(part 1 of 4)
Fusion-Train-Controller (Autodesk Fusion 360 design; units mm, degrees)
parameter "FrameLength" = 640 comment "Fixed existing outer length"
parameter "FrameWidth" = 190 comment "Fixed existing outer width"
parameter "FrameHeight" = 110 comment "Fixed existing height"
parameter "PivotHeight" = 65 comment "Above frame center"
parameter "LeverTravel" = 100 comment "Stable endpoint to endpoint"
parameter "PrintClearance" = 0.3 comment "Prototype diametral running clearance"
base_mesh_feature "Base Mesh Feature"
ground "Pin1"
work_plane "WorkPlane1" AlongDistance -36 ExtraOffset 0
sketch "Flat load-bearing plate" plane through (-36, 0, 0) normal (1, 0, 0) x axis (0, 0, -1)
  line L1 (-33, -55) -> (-33, -75)
  line L2 (2, -55) -> (-33, -55)
  line L3 (2, 55) -> (2, -55)
  line L4 (-33, 55) -> (2, 55)
  line L5 (-33, 75) -> (-33, 55)
  line L6 (-57, 75) -> (-33, 75)
  line L7 (-57, 32) -> (-57, 75)
  line L8 (-86, 26) -> (-57, 32)
  line L9 (-86, -26) -> (-86, 26)
  line L10 (-57, -32) -> (-86, -26)
  line L11 (-57, -75) -> (-57, -32)
  line L12 (-33, -75) -> (-57, -75)
extrude "Extrude1" new body sketch "Flat load-bearing plate" along normal blind 12
work_plane "WorkPlane2" AlongDistance -37 ExtraOffset 0
sketch "Replaceable bushing seat" plane through (-37, 0, 0) normal (1, 0, 0) x axis (0, 0, -1)
  circle C1 centre (-65, 0) radius 10.15
extrude "Extrude2" cut sketch "Replaceable bushing seat" along normal blind 14
work_plane "WorkPlane3" AlongDistance -37 ExtraOffset 0
sketch "Follower pivot bolt" plane through (-37, 0, 0) normal (1, 0, 0) x axis (0, 0, -1)
  circle C1 centre (-12, -35) radius 2.7
extrude "Extrude3" cut sketch "Follower pivot bolt" along normal blind 14
work_plane "WorkPlane4" AlongDistance -76 ExtraOffset 0
sketch "M5 rail mounting bore" plane through (0, -76, 0) normal (0, 1, 0) x axis (1, 0, 0)
  circle C1 centre (-30, -45) radius 2.7
extrude "Extrude4" cut sketch "M5 rail mounting bore" along normal blind 22
work_plane "WorkPlane5" AlongDistance -55 ExtraOffset 0
sketch "Rail screw tool and washer access" plane through (0, -55, 0) normal (0, 1, 0) x axis (1, 0, 0)
  circle C1 centre (-30, -45) radius 5.3
extrude "Extrude5" cut sketch "Rail screw tool and washer access" along normal blind 12
work_plane "WorkPlane6" AlongDistance 54 ExtraOffset 0
sketch "M5 rail mounting bore (1)" plane through (0, 54, 0) normal (0, 1, 0) x axis (1, 0, 0)
  circle C1 centre (-30, -45) radius 2.7
extrude "Extrude6" cut sketch "M5 rail mounting bore (1)" along normal blind 22
work_plane "WorkPlane7" AlongDistance 43 ExtraOffset 0
sketch "Rail screw tool and washer access (1)" plane through (0, 43, 0) normal (0, 1, 0) x axis (1, 0, 0)
  circle C1 centre (-30, -45) radius 5.3
extrude "Extrude7" cut sketch "Rail screw tool and washer access (1)" along normal blind 12
work_plane "WorkPlane8" AlongDistance -37 ExtraOffset 0
sketch "Spring crossblock attachment" plane through (-37, 0, 0) normal (1, 0, 0) x axis (0, 0, -1)
  circle C1 centre (-44, -59) radius 1.7
extrude "Extrude8" cut sketch "Spring crossblock attachment" along normal blind 14
work_plane "WorkPlane9" AlongDistance -37 ExtraOffset 0
sketch "Spring crossblock attachment (1)" plane through (-37, 0, 0) normal (1, 0, 0) x axis (0, 0, -1)
  circle C1 centre (-44, -51) radius 1.7
extrude "Extrude9" cut sketch "Spring crossblock attachment (1)" along normal blind 14
work_plane "WorkPlane1" AlongDistance 24 ExtraOffset 0
sketch "Flat load-bearing plate" plane through (24, 0, 0) normal (1, 0, 0) x axis (0, 0, -1)
  line L1 (-33, -55) -> (-33, -75)
  line L2 (2, -55) -> (-33, -55)
  line L3 (2, 55) -> (2, -55)
  line L4 (-33, 55) -> (2, 55)
  line L5 (-33, 75) -> (-33, 55)
  line L6 (-57, 75) -> (-33, 75)
  line L7 (-57, 32) -> (-57, 75)
  line L8 (-86, 26) -> (-57, 32)
  line L9 (-86, -26) -> (-86, 26)
  line L10 (-57, -32) -> (-86, -26)
  line L11 (-57, -75) -> (-57, -32)
  line L12 (-33, -75) -> (-57, -75)
extrude "Extrude1" new body sketch "Flat load-bearing plate" along normal blind 12
work_plane "WorkPlane2" AlongDistance 23 ExtraOffset 0
sketch "Replaceable bushing seat" plane through (23, 0, 0) normal (1, 0, 0) x axis (0, 0, -1)
  circle C1 centre (-65, 0) radius 10.15
extrude "Extrude2" cut sketch "Replaceable bushing seat" along normal blind 14
work_plane "WorkPlane3" AlongDistance 23 ExtraOffset 0
sketch "Follower pivot bolt" plane through (23, 0, 0) normal (1, 0, 0) x axis (0, 0, -1)
  circle C1 centre (-12, -35) radius 2.7
extrude "Extrude3" cut sketch "Follower pivot bolt" along normal blind 14
work_plane "WorkPlane4" AlongDistance -76 ExtraOffset 0
sketch "M5 rail mounting bore" plane through (0, -76, 0) normal (0, 1, 0) x axis (1, 0, 0)
  circle C1 centre (30, -45) radius 2.7
extrude "Extrude4" cut sketch "M5 rail mounting bore" along normal blind 22
work_plane "WorkPlane5" AlongDistance -55 ExtraOffset 0
sketch "Rail screw tool and washer access" plane through (0, -55, 0) normal (0, 1, 0) x axis (1, 0, 0)
  circle C1 centre (30, -45) radius 5.3
extrude "Extrude5" cut sketch "Rail screw tool and washer access" along normal blind 12
work_plane "WorkPlane6" AlongDistance 54 ExtraOffset 0
sketch "M5 rail mounting bore (1)" plane through (0, 54, 0) normal (0, 1, 0) x axis (1, 0, 0)
  circle C1 centre (30, -45) radius 2.7
extrude "Extrude6" cut sketch "M5 rail mounting bore (1)" along normal blind 22
work_plane "WorkPlane7" AlongDistance 43 ExtraOffset 0
sketch "Rail screw tool and washer access (1)" plane through (0, 43, 0) normal (0, 1, 0) x axis (1, 0, 0)
  circle C1 centre (30, -45) radius 5.3
extrude "Extrude7" cut sketch "Rail screw tool and washer access (1)" along normal blind 12
work_plane "WorkPlane8" AlongDistance 23 ExtraOffset 0
sketch "Spring crossblock attachment" plane through (23, 0, 0) normal (1, 0, 0) x axis (0, 0, -1)
  circle C1 centre (-44, -59) radius 1.7
extrude "Extrude8" cut sketch "Spring crossblock attachment" along normal blind 14
work_plane "WorkPlane9" AlongDistance 23 ExtraOffset 0
sketch "Spring crossblock attachment (1)" plane through (23, 0, 0) normal (1, 0, 0) x axis (0, 0, -1)
  circle C1 centre (-44, -51) radius 1.7
extrude "Extrude9" cut sketch "Spring crossblock attachment (1)" along normal blind 14
work_plane "WorkPlane1" AlongDistance -36 ExtraOffset 0
sketch "Replaceable journal body" plane through (-36, 0, 0) normal (1, 0, 0) x axis (0, 0, -1)
  circle C1 centre (-65, 0) radius 10.05
extrude "Extrude1" new body sketch "Replaceable journal body" along normal blind 12 bodies "P03 Left flanged journal bush"
work_plane "WorkPlane2" AlongDistance -37.2 ExtraOffset 0
sketch "Axial thrust flange" plane through (-37.2, 0, 0) normal (1, 0, 0) x axis (0, 0, -1)
  circle C1 centre (-65, 0) radius 12.75
extrude "Extrude2" add sketch "Axial thrust flange" along normal blind 1.2
work_plane "WorkPlane3" AlongDistance -38 ExtraOffset 0
sketch "Running journal bore" plane through (-38, 0, 0) normal (1, 0, 0) x axis (0, 0, -1)
  circle C1 centre (-65, 0) radius 6.15
extrude "Extrude3" cut sketch "Running journal bore" along normal blind 15
work_plane "WorkPlane1" AlongDistance 24 ExtraOffset 0
sketch "Replaceable journal body" plane through (24, 0, 0) normal (1, 0, 0) x axis (0, 0, -1)
  circle C1 centre (-65, 0) radius 10.05
extrude "Extrude1" new body sketch "Replaceable journal body" along normal blind 12 bodies "P04 Right flanged journal bush"
work_plane "WorkPlane2" AlongDistance 36 ExtraOffset 0
sketch "Axial thrust flange" plane through (36, 0, 0) normal (1, 0, 0) x axis (0, 0, -1)
  circle C1 centre (-65, 0) radius 12.75
extrude "Extrude2" add sketch "Axial thrust flange" along normal blind 1.2
work_plane "WorkPlane3" AlongDistance 23 ExtraOffset 0
sketch "Running journal bore" plane through (23, 0, 0) normal (1, 0, 0) x axis (0, 0, -1)
  circle C1 centre (-65, 0) radius 6.15
extrude "Extrude3" cut sketch "Running journal bore" along normal blind 15
work_plane "WorkPlane1" AlongDistance -37.35 ExtraOffset 0
sketch "Continuous 12 mm journals" plane through (-37.35, 0, 0) normal (1, 0, 0) x axis (0, 0, -1)
  circle C1 centre (-65, 0) radius 6
extrude "Extrude1" new body sketch "Continuous 12 mm journals" along normal blind 74.7 bodies "P05 Printed main shaft - horizontal print"
work_plane "WorkPlane2" AlongDistance -23.8 ExtraOffset 0
sketch "16 mm structural shaft" plane through (-23.8, 0, 0) normal (1, 0, 0) x axis (0, 0, -1)
  circle C1 centre (-65, 0) radius 8
extrude "Extrude2" add sketch "16 mm structural shaft" along normal blind 47.6
work_plane "WorkPlane3" AlongDistance -23.9 ExtraOffset 0
sketch "D-flat torque key" plane through (-23.9, 0, 0) normal (1, 0, 0) x axis (0, 0, -1)
  line L1 (-56, 9) -> (-56, 6.5)
  line L2 (-74, 9) -> (-56, 9)
  line L3 (-74, 6.5) -> (-74, 9)
  line L4 (-56, 6.5) -> (-74, 6.5)
extrude "Extrude3" cut sketch "D-flat torque key" along normal blind 47.8
work_plane "WorkPlane4" AlongDistance 37.35 ExtraOffset 0
sketch "Integral axial shoulder" plane through (37.35, 0, 0) normal (1, 0, 0) x axis (0, 0, -1)
  circle C1 centre (-65, 0) radius 10
extrude "Extrude4" add sketch "Integral axial shoulder" along normal blind 3
work_plane "WorkPlane5" AlongDistance 40.35 ExtraOffset 0
sketch "Sensor drive stub" plane through (40.35, 0, 0) normal (1, 0, 0) x axis (0, 0, -1)
  circle C1 centre (-65, 0) radius 4
extrude "Extrude5" add sketch "Sensor drive stub" along normal blind 10
work_plane "WorkPlane6" AlongDistance 40.25 ExtraOffset 0
sketch "Sensor drive flat" plane through (40.25, 0, 0) normal (1, 0, 0) x axis (0, 0, -1)
  line L1 (-60, 5) -> (-60, 3.2)
  line L2 (-70, 5) -> (-60, 5)
  line L3 (-70, 3.2) -> (-70, 5)
  line L4 (-60, 3.2) -> (-70, 3.2)
extrude "Extrude6" cut sketch "Sensor drive flat" along normal blind 10.25
work_plane "WorkPlane7" AlongDistance -37.45 ExtraOffset 0
sketch "M3 heat-set end retention" plane through (-37.45, 0, 0) normal (1, 0, 0) x axis (0, 0, -1)
  circle C1 centre (-65, 0) radius 2
extrude "Extrude7" cut sketch "M3 heat-set end retention" along normal blind 6.8
work_plane "WorkPlane1" AlongDistance -39.35 ExtraOffset 0
sketch "Axial cap" plane through (-39.35, 0, 0) normal (1, 0, 0) x axis (0, 0, -1)
  circle C1 centre (-65, 0) radius 10
extrude "Extrude1" new body sketch "Axial cap" along normal blind 2 bodies "P06 Shaft retaining cap"
work_plane "WorkPlane2" AlongDistance -39.5 ExtraOffset 0
sketch "M3 cap screw" plane through (-39.5, 0, 0) normal (1, 0, 0) x axis (0, 0, -1)
  circle C1 centre (-65, 0) radius 1.7
extrude "Extrude2" cut sketch "M3 cap screw" along normal blind 2.4
work_plane "WorkPlane1" AlongDistance -7 ExtraOffset 0
sketch "Main lever hub" plane through (-7, 0, 0) normal (1, 0, 0) x axis (0, 0, -1)
  circle C1 centre (-65, 0) radius 22
extrude "Extrude1" new body sketch "Main lever hub" along normal blind 14 bodies "P07 Integral lever rotor and cam carrier"
work_plane "WorkPlane2" AlongDistance -7 ExtraOffset 0
sketch "Continuous reinforced lever stem" plane through (-7, 0, 0) normal (1, 0, 0) x axis (0, 0, -1)
  line L1 (-60, 14) -> (-60, -14)
  line L2 (-95, 11) -> (-60, 14)
  line L3 (-150, 7) -> (-95, 11)
  line L4 (-195, 7) -> (-150, 7)
  line L5 (-195, -7) -> (-195, 7)
  line L6 (-150, -7) -> (-195, -7)
  line L7 (-95, -11) -> (-150, -7)
  line L8 (-60, -14) -> (-95, -11)
extrude "Extrude2" add sketch "Continuous reinforced lever stem" along normal blind 14
work_plane "WorkPlane3" AlongDistance -7 ExtraOffset 0
sketch "Integrated cam carrier fan" plane through (-7, 0, 0) normal (1, 0, 0) x axis (0, 0, -1)
  line L1 (-44.5, 35.507) -> (-65, 0)
  line L2 (-42.6698, 34.3855) -> (-44.5, 35.507)
  line L3 (-40.9008, 33.1697) -> (-42.6698, 34.3855)
  line L4 (-39.1979, 31.863) -> (-40.9008, 33.1697)
  line L5 (-37.5656, 30.4689) -> (-39.1979, 31.863)
  line L6 (-36.0086, 28.9914) -> (-37.5656, 30.4689)
  line L7 (-34.5311, 27.4344) -> (-36.0086, 28.9914)
  line L8 (-33.137, 25.8021) -> (-34.5311, 27.4344)
  line L9 (-31.8303, 24.0992) -> (-33.137, 25.8021)
  line L10 (-30.6145, 22.3302) -> (-31.8303, 24.0992)
  line L11 (-29.493, 20.5) -> (-30.6145, 22.3302)
  line L12 (-28.4687, 18.6136) -> (-29.493, 20.5)
  line L13 (-27.5446, 16.6762) -> (-28.4687, 18.6136)
  line L14 (-26.7232, 14.6931) -> (-27.5446, 16.6762)
  line L15 (-26.0067, 12.6697) -> (-26.7232, 14.6931)
  line L16 (-25.397, 10.6116) -> (-26.0067, 12.6697)
  line L17 (-24.8959, 8.5244) -> (-25.397, 10.6116)
  line L18 (-24.5048, 6.4138) -> (-24.8959, 8.5244)
  line L19 (-24.2246, 4.2857) -> (-24.5048, 6.4138)
  line L20 (-24.0562, 2.1458) -> (-24.2246, 4.2857)
  line L21 (-24, 0) -> (-24.0562, 2.1458)
  line L22 (-24.0562, -2.1458) -> (-24, 0)
  line L23 (-24.2246, -4.2857) -> (-24.0562, -2.1458)
  line L24 (-24.5048, -6.4138) -> (-24.2246, -4.2857)
  line L25 (-24.8959, -8.5244) -> (-24.5048, -6.4138)
  line L26 (-25.397, -10.6116) -> (-24.8959, -8.5244)
  line L27 (-26.0067, -12.6697) -> (-25.397, -10.6116)
  line L28 (-26.7232, -14.6931) -> (-26.0067, -12.6697)
  line L29 (-27.5446, -16.6762) -> (-26.7232, -14.6931)
  line L30 (-28.4687, -18.6136) -> (-27.5446, -16.6762)
  line L31 (-29.493, -20.5) -> (-28.4687, -18.6136)
  line L32 (-30.6145, -22.3302) -> (-29.493, -20.5)
  line L33 (-31.8303, -24.0992) -> (-30.6145, -22.3302)
  line L34 (-33.137, -25.8021) -> (-31.8303, -24.0992)
  line L35 (-34.5311, -27.4344) -> (-33.137, -25.8021)
  line L36 (-36.0086, -28.9914) -> (-34.5311, -27.4344)
  line L37 (-37.5656, -30.4689) -> (-36.0086, -28.9914)
  line L38 (-39.1979, -31.863) -> (-37.5656, -30.4689)
  line L39 (-40.9008, -33.1697) -> (-39.1979, -31.863)
  line L40 (-42.6698, -34.3855) -> (-40.9008, -33.1697)
  line L41 (-44.5, -35.507) -> (-42.6698, -34.3855)
  line L42 (-65, 0) -> (-44.5, -35.507)
extrude "Extrude3" add sketch "Integrated cam carrier fan" along normal blind 14
work_plane "WorkPlane4" AlongDistance -23.6 ExtraOffset 0
sketch "Integral axial locating hub" plane through (-23.6, 0, 0) normal (1, 0, 0) x axis (0, 0, -1)
  circle C1 centre (-65, 0) radius 10
work_plane "WorkPlane5" AlongDistance -24 ExtraOffset 0
sketch "D shaft socket" plane through (-24, 0, 0) normal (1, 0, 0) x axis (0, 0, -1)
  line L1 (-69.6247, 6.65) -> (-60.3753, 6.65)
  arc A1 centre (-65, 0) radius 8.1 clockwise from (-60.3753, 6.65) to (-69.6247, 6.65)
extrude "Extrude5" cut sketch "D shaft socket" along normal blind 48
work_plane "WorkPlane6" AlongDistance 0.3 ExtraOffset 0
sketch "Cam M3 insert pocket" plane through (0.3, 0, 0) normal (1, 0, 0) x axis (0, 0, -1)
  circle C1 centre (-39.5442, 25.4558) radius 2
extrude "Extrude6" cut sketch "Cam M3 insert pocket" along normal blind 6.8
work_plane "WorkPlane7" AlongDistance 0.3 ExtraOffset 0
sketch "Cam M3 insert pocket (1)" plane through (0.3, 0, 0) normal (1, 0, 0) x axis (0, 0, -1)
  circle C1 centre (-29, 0) radius 2
extrude "Extrude7" cut sketch "Cam M3 insert pocket (1)" along normal blind 6.8
work_plane "WorkPlane8" AlongDistance 0.3 ExtraOffset 0
sketch "Cam M3 insert pocket (2)" plane through (0.3, 0, 0) normal (1, 0, 0) x axis (0, 0, -1)
  circle C1 centre (-39.5442, -25.4558) radius 2
extrude "Extrude8" cut sketch "Cam M3 insert pocket (2)" along normal blind 6.8
work_plane "WorkPlane9" AlongDistance -8 ExtraOffset 0
sketch "Grip through bolt" plane through (-8, 0, 0) normal (1, 0, 0) x axis (0, 0, -1)
  circle C1 centre (-180, 0) radius 1.7
extrude "Extrude9" cut sketch "Grip through bolt" along normal blind 16
work_plane "WorkPlane10" AlongDistance -8 ExtraOffset 0
sketch "Grip through bolt (1)" plane through (-8, 0, 0) normal (1, 0, 0) x axis (0, 0, -1)
  circle C1 centre (-190, 0) radius 1.7
extrude "Extrude10" cut sketch "Grip through bolt (1)" along normal blind 16
work_plane "WorkPlane1" AlongDistance 7 ExtraOffset 0
sketch "Roller compensated replaceable cam" plane through (7, 0, 0) normal (1, 0, 0) x axis (0, 0, -1)
  line L1 (-39.4967, 42.2602) -> (-39.6212, 42.3096)
  line L2 (-39.3834, 42.211) -> (-39.4967, 42.2602)
  line L3 (-39.2796, 42.1617) -> (-39.3834, 42.211)
  line L4 (-39.1836, 42.1119) -> (-39.2796, 42.1617)
  line L5 (-39.0932, 42.0608) -> (-39.1836, 42.1119)
  line L6 (-39.0065, 42.0075) -> (-39.0932, 42.0608)
  line L7 (-38.9215, 41.9508) -> (-39.0065, 42.0075)
  line L8 (-38.8363, 41.8895) -> (-38.9215, 41.9508)
  line L9 (-38.7492, 41.8219) -> (-38.8363, 41.8895)
  line L10 (-38.6586, 41.7465) -> (-38.7492, 41.8219)
  line L11 (-38.5633, 41.6619) -> (-38.6586, 41.7465)
  line L12 (-38.4623, 41.5665) -> (-38.5633, 41.6619)
  line L13 (-38.3549, 41.459) -> (-38.4623, 41.5665)
  line L14 (-38.2404, 41.3384) -> (-38.3549, 41.459)
  line L15 (-38.1184, 41.204) -> (-38.2404, 41.3384)
  line L16 (-37.9886, 41.055) -> (-38.1184, 41.204)
  line L17 (-37.8508, 40.8913) -> (-37.9886, 41.055)
  line L18 (-37.7045, 40.7127) -> (-37.8508, 40.8913)
  line L19 (-37.5496, 40.5196) -> (-37.7045, 40.7127)
  line L20 (-37.3856, 40.3123) -> (-37.5496, 40.5196)
  line L21 (-37.2122, 40.0915) -> (-37.3856, 40.3123)
  line L22 (-37.0289, 39.858) -> (-37.2122, 40.0915)
  line L23 (-36.8353, 39.6128) -> (-37.0289, 39.858)
  line L24 (-36.6306, 39.3571) -> (-36.8353, 39.6128)
  line L25 (-36.4145, 39.0923) -> (-36.6306, 39.3571)
  line L26 (-36.1865, 38.82) -> (-36.4145, 39.0923)
  line L27 (-35.9461, 38.5417) -> (-36.1865, 38.82)
  line L28 (-35.6932, 38.2594) -> (-35.9461, 38.5417)
  line L29 (-35.4277, 37.9751) -> (-35.6932, 38.2594)
  line L30 (-35.15, 37.6908) -> (-35.4277, 37.9751)
  line L31 (-34.8607, 37.4087) -> (-35.15, 37.6908)
  line L32 (-34.5606, 37.1307) -> (-34.8607, 37.4087)
  line L33 (-34.2512, 36.859) -> (-34.5606, 37.1307)
  line L34 (-33.934, 36.5953) -> (-34.2512, 36.859)
  line L35 (-33.6109, 36.341) -> (-33.934, 36.5953)
  line L36 (-33.2841, 36.0975) -> (-33.6109, 36.341)
  line L37 (-32.9558, 35.8655) -> (-33.2841, 36.0975)
  line L38 (-32.6282, 35.6454) -> (-32.9558, 35.8655)
  line L39 (-32.3036, 35.4375) -> (-32.6282, 35.6454)
  line L40 (-31.984, 35.2415) -> (-32.3036, 35.4375)
  line L41 (-31.6712, 35.057) -> (-31.984, 35.2415)
  line L42 (-31.3671, 34.8833) -> (-31.6712, 35.057)
  line L43 (-31.073, 34.7197) -> (-31.3671, 34.8833)
  line L44 (-30.7902, 34.5655) -> (-31.073, 34.7197)
  line L45 (-30.52, 34.4197) -> (-30.7902, 34.5655)
  line L46 (-30.263, 34.2816) -> (-30.52, 34.4197)
  line L47 (-30.0201, 34.1506) -> (-30.263, 34.2816)
  line L48 (-29.7919, 34.0259) -> (-30.0201, 34.1506)
  line L49 (-29.5787, 33.9071) -> (-29.7919, 34.0259)
  line L50 (-29.3807, 33.7939) -> (-29.5787, 33.9071)
  line L51 (-29.1982, 33.6858) -> (-29.3807, 33.7939)
  line L52 (-29.0309, 33.5827) -> (-29.1982, 33.6858)
  line L53 (-28.8786, 33.4843) -> (-29.0309, 33.5827)
  line L54 (-28.7406, 33.3906) -> (-28.8786, 33.4843)
  line L55 (-28.6164, 33.3013) -> (-28.7406, 33.3906)
  line L56 (-28.5047, 33.2161) -> (-28.6164, 33.3013)
  line L57 (-28.4046, 33.1346) -> (-28.5047, 33.2161)
  line L58 (-28.3144, 33.0563) -> (-28.4046, 33.1346)
  line L59 (-28.2327, 32.9802) -> (-28.3144, 33.0563)
  line L60 (-28.1577, 32.9052) -> (-28.2327, 32.9802)
  line L61 (-28.0879, 32.8301) -> (-28.1577, 32.9052)
  line L62 (-28.0214, 32.7532) -> (-28.0879, 32.8301)
  line L63 (-27.9569, 32.6728) -> (-28.0214, 32.7532)
  line L64 (-27.893, 32.5869) -> (-27.9569, 32.6728)
  line L65 (-27.8285, 32.4936) -> (-27.893, 32.5869)
  line L66 (-27.7627, 32.3911) -> (-27.8285, 32.4936)
  line L67 (-27.6947, 32.2776) -> (-27.7627, 32.3911)
  line L68 (-27.6241, 32.1514) -> (-27.6947, 32.2776)
  line L69 (-27.5507, 32.0113) -> (-27.6241, 32.1514)
  line L70 (-27.4742, 31.8562) -> (-27.5507, 32.0113)
  line L71 (-27.3945, 31.6853) -> (-27.4742, 31.8562)
  line L72 (-27.3113, 31.4981) -> (-27.3945, 31.6853)
  line L73 (-27.2245, 31.2943) -> (-27.3113, 31.4981)
  line L74 (-27.1338, 31.074) -> (-27.2245, 31.2943)
  line L75 (-27.0388, 30.8373) -> (-27.1338, 31.074)
  line L76 (-26.939, 30.5847) -> (-27.0388, 30.8373)
  line L77 (-26.8337, 30.3166) -> (-26.939, 30.5847)
  line L78 (-26.7223, 30.034) -> (-26.8337, 30.3166)
  line L79 (-26.6038, 29.7375) -> (-26.7223, 30.034)
  line L80 (-26.4775, 29.4284) -> (-26.6038, 29.7375)
  line L81 (-26.3424, 29.1079) -> (-26.4775, 29.4284)
  line L82 (-26.1977, 28.7772) -> (-26.3424, 29.1079)
  line L83 (-26.0425, 28.4382) -> (-26.1977, 28.7772)
  line L84 (-25.8761, 28.0925) -> (-26.0425, 28.4382)
  line L85 (-25.6981, 27.7422) -> (-25.8761, 28.0925)
  line L86 (-25.5084, 27.3893) -> (-25.6981, 27.7422)
  line L87 (-25.3069, 27.0362) -> (-25.5084, 27.3893)
  line L88 (-25.0943, 26.6851) -> (-25.3069, 27.0362)
  line L89 (-24.8713, 26.3382) -> (-25.0943, 26.6851)
  line L90 (-24.6392, 25.9976) -> (-24.8713, 26.3382)
  line L91 (-24.3995, 25.6653) -> (-24.6392, 25.9976)
  line L92 (-24.1539, 25.3428) -> (-24.3995, 25.6653)
  line L93 (-23.9045, 25.0314) -> (-24.1539, 25.3428)
  line L94 (-23.6532, 24.7321) -> (-23.9045, 25.0314)
  line L95 (-23.4022, 24.4455) -> (-23.6532, 24.7321)
  line L96 (-23.1534, 24.1718) -> (-23.4022, 24.4455)
  line L97 (-22.9088, 23.9111) -> (-23.1534, 24.1718)
  line L98 (-22.6701, 23.6631) -> (-22.9088, 23.9111)
  line L99 (-22.4387, 23.4276) -> (-22.6701, 23.6631)
  line L100 (-22.2162, 23.204) -> (-22.4387, 23.4276)
  line L101 (-22.0036, 22.9918) -> (-22.2162, 23.204)
  line L102 (-21.8021, 22.7907) -> (-22.0036, 22.9918)
  line L103 (-21.6123, 22.6001) -> (-21.8021, 22.7907)
  line L104 (-21.435, 22.4197) -> (-21.6123, 22.6001)
  line L105 (-21.2706, 22.2491) -> (-21.435, 22.4197)
  line L106 (-21.1193, 22.088) -> (-21.2706, 22.2491)
  line L107 (-20.9813, 21.9362) -> (-21.1193, 22.088)
  line L108 (-20.8565, 21.7934) -> (-20.9813, 21.9362)
  line L109 (-20.7443, 21.6594) -> (-20.8565, 21.7934)
  line L110 (-20.6444, 21.5337) -> (-20.7443, 21.6594)
  line L111 (-20.556, 21.4159) -> (-20.6444, 21.5337)
  line L112 (-20.478, 21.3055) -> (-20.556, 21.4159)
  line L113 (-20.4094, 21.2014) -> (-20.478, 21.3055)
  line L114 (-20.349, 21.1027) -> (-20.4094, 21.2014)
  line L115 (-20.2954, 21.0079) -> (-20.349, 21.1027)
  line L116 (-20.2475, 20.9154) -> (-20.2954, 21.0079)
  line L117 (-20.2039, 20.8234) -> (-20.2475, 20.9154)
  line L118 (-20.1637, 20.7297) -> (-20.2039, 20.8234)
  line L119 (-20.126, 20.6321) -> (-20.1637, 20.7297)
  line L120 (-20.0901, 20.5286) -> (-20.126, 20.6321)
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extrude "Extrude1" new body sketch "Roller compensated replaceable cam" along normal blind 8 bodies "P08 Cam 7 gates - stable endpoints"
work_plane "WorkPlane2" AlongDistance 6.9 ExtraOffset 0
sketch "Cam screw clearance" plane through (6.9, 0, 0) normal (1, 0, 0) x axis (0, 0, -1)
  circle C1 centre (-39.5442, 25.4558) radius 1.7
extrude "Extrude2" cut sketch "Cam screw clearance" along normal blind 8.2
work_plane "WorkPlane3" AlongDistance 12 ExtraOffset 0
sketch "Cam head recess" plane through (12, 0, 0) normal (1, 0, 0) x axis (0, 0, -1)
  circle C1 centre (-39.5442, 25.4558) radius 3.1
extrude "Extrude3" cut sketch "Cam head recess" along normal blind 3.1
work_plane "WorkPlane4" AlongDistance 6.9 ExtraOffset 0
sketch "Cam screw clearance (1)" plane through (6.9, 0, 0) normal (1, 0, 0) x axis (0, 0, -1)
  circle C1 centre (-29, 0) radius 1.7
extrude "Extrude4" cut sketch "Cam screw clearance (1)" along normal blind 8.2
work_plane "WorkPlane5" AlongDistance 12 ExtraOffset 0
sketch "Cam head recess (1)" plane through (12, 0, 0) normal (1, 0, 0) x axis (0, 0, -1)
  circle C1 centre (-29, 0) radius 3.1
extrude "Extrude5" cut sketch "Cam head recess (1)" along normal blind 3.1
work_plane "WorkPlane6" AlongDistance 6.9 ExtraOffset 0
sketch "Cam screw clearance (2)" plane through (6.9, 0, 0) normal (1, 0, 0) x axis (0, 0, -1)
  circle C1 centre (-39.5442, -25.4558) radius 1.7
extrude "Extrude6" cut sketch "Cam screw clearance (2)" along normal blind 8.2
work_plane "WorkPlane7" AlongDistance 12 ExtraOffset 0
sketch "Cam head recess (2)" plane through (12, 0, 0) normal (1, 0, 0) x axis (0, 0, -1)
  circle C1 centre (-39.5442, -25.4558) radius 3.1
extrude "Extrude7" cut sketch "Cam head recess (2)" along normal blind 3.1
work_plane "WorkPlane1" AlongDistance 7 ExtraOffset 0
sketch "Roller compensated replaceable cam" plane through (7, 0, 0) normal (1, 0, 0) x axis (0, 0, -1)
  line L1 (-40.6423, 42.8316) -> (-40.8055, 42.9534)
  line L2 (-40.4783, 42.705) -> (-40.6423, 42.8316)
  line L3 (-40.3132, 42.5736) -> (-40.4783, 42.705)
  line L4 (-40.1469, 42.4372) -> (-40.3132, 42.5736)
  line L5 (-39.9791, 42.2958) -> (-40.1469, 42.4372)
  line L6 (-39.8097, 42.1493) -> (-39.9791, 42.2958)
  line L7 (-39.6386, 41.9977) -> (-39.8097, 42.1493)
  line L8 (-39.4656, 41.8411) -> (-39.6386, 41.9977)
  line L9 (-39.2906, 41.6794) -> (-39.4656, 41.8411)
  line L10 (-39.1134, 41.5128) -> (-39.2906, 41.6794)
  line L11 (-38.9338, 41.3413) -> (-39.1134, 41.5128)
  line L12 (-38.7519, 41.165) -> (-38.9338, 41.3413)
  line L13 (-38.5674, 40.9842) -> (-38.7519, 41.165)
  line L14 (-38.3803, 40.7991) -> (-38.5674, 40.9842)
  line L15 (-38.1904, 40.6097) -> (-38.3803, 40.7991)
  line L16 (-37.9976, 40.4164) -> (-38.1904, 40.6097)
  line L17 (-37.8019, 40.2195) -> (-37.9976, 40.4164)
  line L18 (-37.6031, 40.0191) -> (-37.8019, 40.2195)
  line L19 (-37.4011, 39.8157) -> (-37.6031, 40.0191)
  line L20 (-37.1958, 39.6094) -> (-37.4011, 39.8157)
  line L21 (-36.9872, 39.4008) -> (-37.1958, 39.6094)
  line L22 (-36.7753, 39.19) -> (-36.9872, 39.4008)
  line L23 (-36.5599, 38.9775) -> (-36.7753, 39.19)
  line L24 (-36.3411, 38.7636) -> (-36.5599, 38.9775)
  line L25 (-36.1189, 38.5488) -> (-36.3411, 38.7636)
  line L26 (-35.8933, 38.3333) -> (-36.1189, 38.5488)
  line L27 (-35.6644, 38.1177) -> (-35.8933, 38.3333)
  line L28 (-35.4322, 37.9021) -> (-35.6644, 38.1177)
  line L29 (-35.197, 37.6871) -> (-35.4322, 37.9021)
  line L30 (-34.9588, 37.473) -> (-35.197, 37.6871)
  line L31 (-34.7178, 37.2602) -> (-34.9588, 37.473)
  line L32 (-34.4743, 37.0489) -> (-34.7178, 37.2602)
  line L33 (-34.2286, 36.8395) -> (-34.4743, 37.0489)
  line L34 (-33.9808, 36.6322) -> (-34.2286, 36.8395)
  line L35 (-33.7314, 36.4274) -> (-33.9808, 36.6322)
  line L36 (-33.4806, 36.2252) -> (-33.7314, 36.4274)
  line L37 (-33.2289, 36.0258) -> (-33.4806, 36.2252)
  line L38 (-32.9765, 35.8294) -> (-33.2289, 36.0258)
  line L39 (-32.7239, 35.6361) -> (-32.9765, 35.8294)
  line L40 (-32.4714, 35.446) -> (-32.7239, 35.6361)
  line L41 (-32.2195, 35.259) -> (-32.4714, 35.446)
  line L42 (-31.9685, 35.0753) -> (-32.2195, 35.259)
  line L43 (-31.7188, 34.8948) -> (-31.9685, 35.0753)
  line L44 (-31.4708, 34.7175) -> (-31.7188, 34.8948)
  line L45 (-31.2249, 34.5432) -> (-31.4708, 34.7175)
  line L46 (-30.9813, 34.3719) -> (-31.2249, 34.5432)
  line L47 (-30.7405, 34.2034) -> (-30.9813, 34.3719)
  line L48 (-30.5027, 34.0377) -> (-30.7405, 34.2034)
  line L49 (-30.2682, 33.8746) -> (-30.5027, 34.0377)
  line L50 (-30.0373, 33.7139) -> (-30.2682, 33.8746)
  line L51 (-29.8103, 33.5555) -> (-30.0373, 33.7139)
  line L52 (-29.5875, 33.3992) -> (-29.8103, 33.5555)
  line L53 (-29.3689, 33.2448) -> (-29.5875, 33.3992)
  line L54 (-29.1548, 33.0923) -> (-29.3689, 33.2448)
  line L55 (-28.9455, 32.9414) -> (-29.1548, 33.0923)
  line L56 (-28.7409, 32.7921) -> (-28.9455, 32.9414)
  line L57 (-28.5413, 32.644) -> (-28.7409, 32.7921)
  line L58 (-28.3468, 32.4972) -> (-28.5413, 32.644)
  line L59 (-28.1574, 32.3515) -> (-28.3468, 32.4972)
  line L60 (-27.9732, 32.2068) -> (-28.1574, 32.3515)
  line L61 (-27.7942, 32.0628) -> (-27.9732, 32.2068)
  line L62 (-27.6204, 31.9196) -> (-27.7942, 32.0628)
  line L63 (-27.4518, 31.7769) -> (-27.6204, 31.9196)
  line L64 (-27.2884, 31.6347) -> (-27.4518, 31.7769)
  line L65 (-27.1301, 31.4927) -> (-27.2884, 31.6347)
  line L66 (-26.9767, 31.351) -> (-27.1301, 31.4927)
  line L67 (-26.8282, 31.2092) -> (-26.9767, 31.351)
  line L68 (-26.6843, 31.0673) -> (-26.8282, 31.2092)
  line L69 (-26.545, 30.925) -> (-26.6843, 31.0673)
  line L70 (-26.4101, 30.7822) -> (-26.545, 30.925)
  line L71 (-26.2793, 30.6387) -> (-26.4101, 30.7822)
  line L72 (-26.1524, 30.4942) -> (-26.2793, 30.6387)
  line L73 (-26.0293, 30.3485) -> (-26.1524, 30.4942)
  line L74 (-25.9096, 30.2013) -> (-26.0293, 30.3485)
  line L75 (-25.7932, 30.0524) -> (-25.9096, 30.2013)
  line L76 (-25.6797, 29.9015) -> (-25.7932, 30.0524)
  line L77 (-25.5691, 29.7482) -> (-25.6797, 29.9015)
  line L78 (-25.461, 29.5923) -> (-25.5691, 29.7482)
  line L79 (-25.3553, 29.4334) -> (-25.461, 29.5923)
  line L80 (-25.2517, 29.2713) -> (-25.3553, 29.4334)
  line L81 (-25.15, 29.1057) -> (-25.2517, 29.2713)
  line L82 (-25.0502, 28.9363) -> (-25.15, 29.1057)
  line L83 (-24.9519, 28.7628) -> (-25.0502, 28.9363)
  line L84 (-24.855, 28.5849) -> (-24.9519, 28.7628)
  line L85 (-24.7595, 28.4024) -> (-24.855, 28.5849)
  line L86 (-24.665, 28.2152) -> (-24.7595, 28.4024)
  line L87 (-24.5716, 28.023) -> (-24.665, 28.2152)
  line L88 (-24.4791, 27.8257) -> (-24.5716, 28.023)
  line L89 (-24.3873, 27.6231) -> (-24.4791, 27.8257)
  line L90 (-24.2961, 27.4152) -> (-24.3873, 27.6231)
  line L91 (-24.2054, 27.2019) -> (-24.2961, 27.4152)
  line L92 (-24.115, 26.9832) -> (-24.2054, 27.2019)
  line L93 (-24.0247, 26.7591) -> (-24.115, 26.9832)
  line L94 (-23.9346, 26.5296) -> (-24.0247, 26.7591)
  line L95 (-23.8442, 26.2947) -> (-23.9346, 26.5296)
  line L96 (-23.7536, 26.0546) -> (-23.8442, 26.2947)
  line L97 (-23.6625, 25.8094) -> (-23.7536, 26.0546)
  line L98 (-23.5707, 25.5592) -> (-23.6625, 25.8094)
  line L99 (-23.478, 25.3041) -> (-23.5707, 25.5592)
  line L100 (-23.3842, 25.0444) -> (-23.478, 25.3041)
  line L101 (-23.2891, 24.7802) -> (-23.3842, 25.0444)
  line L102 (-23.1926, 24.5118) -> (-23.2891, 24.7802)
  line L103 (-23.0943, 24.2394) -> (-23.1926, 24.5118)
  line L104 (-22.9942, 23.9633) -> (-23.0943, 24.2394)
  line L105 (-22.8919, 23.6838) -> (-22.9942, 23.9633)
  line L106 (-22.7873, 23.4012) -> (-22.8919, 23.6838)
  line L107 (-22.6803, 23.1157) -> (-22.7873, 23.4012)
  line L108 (-22.5706, 22.8278) -> (-22.6803, 23.1157)
  line L109 (-22.4581, 22.5379) -> (-22.5706, 22.8278)
  line L110 (-22.3428, 22.2461) -> (-22.4581, 22.5379)
  line L111 (-22.2245, 21.953) -> (-22.3428, 22.2461)
  line L112 (-22.1031, 21.659) -> (-22.2245, 21.953)
  line L113 (-21.9788, 21.3644) -> (-22.1031, 21.659)
  line L114 (-21.8513, 21.0696) -> (-21.9788, 21.3644)
  line L115 (-21.7209, 20.7751) -> (-21.8513, 21.0696)
  line L116 (-21.5876, 20.4811) -> (-21.7209, 20.7751)
  line L117 (-21.4516, 20.1882) -> (-21.5876, 20.4811)
  line L118 (-21.3129, 19.8966) -> (-21.4516, 20.1882)
  line L119 (-21.1718, 19.6067) -> (-21.3129, 19.8966)
  line L120 (-21.0286, 19.3189) -> (-21.1718, 19.6067)
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extrude "Extrude1" new body sketch "Roller compensated replaceable cam" along normal blind 8 bodies "P08 Cam 5 gates - stable endpoints"
work_plane "WorkPlane2" AlongDistance 6.9 ExtraOffset 0
sketch "Cam screw clearance" plane through (6.9, 0, 0) normal (1, 0, 0) x axis (0, 0, -1)
  circle C1 centre (-39.5442, 25.4558) radius 1.7
extrude "Extrude2" cut sketch "Cam screw clearance" along normal blind 8.2
work_plane "WorkPlane3" AlongDistance 12 ExtraOffset 0
sketch "Cam head recess" plane through (12, 0, 0) normal (1, 0, 0) x axis (0, 0, -1)
  circle C1 centre (-39.5442, 25.4558) radius 3.1
extrude "Extrude3" cut sketch "Cam head recess" along normal blind 3.1
work_plane "WorkPlane4" AlongDistance 6.9 ExtraOffset 0
sketch "Cam screw clearance (1)" plane through (6.9, 0, 0) normal (1, 0, 0) x axis (0, 0, -1)
  circle C1 centre (-29, 0) radius 1.7
extrude "Extrude4" cut sketch "Cam screw clearance (1)" along normal blind 8.2
work_plane "WorkPlane5" AlongDistance 12 ExtraOffset 0
sketch "Cam head recess (1)" plane through (12, 0, 0) normal (1, 0, 0) x axis (0, 0, -1)
  circle C1 centre (-29, 0) radius 3.1
extrude "Extrude5" cut sketch "Cam head recess (1)" along normal blind 3.1
work_plane "WorkPlane6" AlongDistance 6.9 ExtraOffset 0
sketch "Cam screw clearance (2)" plane through (6.9, 0, 0) normal (1, 0, 0) x axis (0, 0, -1)
  circle C1 centre (-39.5442, -25.4558) radius 1.7
extrude "Extrude6" cut sketch "Cam screw clearance (2)" along normal blind 8.2
work_plane "WorkPlane7" AlongDistance 12 ExtraOffset 0
sketch "Cam head recess (2)" plane through (12, 0, 0) normal (1, 0, 0) x axis (0, 0, -1)
  circle C1 centre (-39.5442, -25.4558) radius 3.1
extrude "Extrude7" cut sketch "Cam head recess (2)" along normal blind 3.1
work_plane "WorkPlane1" AlongDistance 7 ExtraOffset 0
sketch "Roller compensated replaceable cam" plane through (7, 0, 0) normal (1, 0, 0) x axis (0, 0, -1)
  line L1 (-40.92, 42.0772) -> (-41.1325, 42.2273)
  line L2 (-40.7077, 41.9259) -> (-40.92, 42.0772)
  line L3 (-40.4956, 41.7734) -> (-40.7077, 41.9259)
  line L4 (-40.2838, 41.6199) -> (-40.4956, 41.7734)
  line L5 (-40.0721, 41.4654) -> (-40.2838, 41.6199)
  line L6 (-39.8606, 41.3098) -> (-40.0721, 41.4654)
  line L7 (-39.6492, 41.1532) -> (-39.8606, 41.3098)
  line L8 (-39.4381, 40.9957) -> (-39.6492, 41.1532)
  line L9 (-39.2271, 40.8372) -> (-39.4381, 40.9957)
  line L10 (-39.0163, 40.6779) -> (-39.2271, 40.8372)
  line L11 (-38.8057, 40.5176) -> (-39.0163, 40.6779)
  line L12 (-38.5952, 40.3566) -> (-38.8057, 40.5176)
  line L13 (-38.3849, 40.1947) -> (-38.5952, 40.3566)
  line L14 (-38.1747, 40.032) -> (-38.3849, 40.1947)
  line L15 (-37.9647, 39.8686) -> (-38.1747, 40.032)
  line L16 (-37.7549, 39.7045) -> (-37.9647, 39.8686)
  line L17 (-37.5452, 39.5397) -> (-37.7549, 39.7045)
  line L18 (-37.3357, 39.3742) -> (-37.5452, 39.5397)
  line L19 (-37.1263, 39.2081) -> (-37.3357, 39.3742)
  line L20 (-36.9171, 39.0413) -> (-37.1263, 39.2081)
  line L21 (-36.7081, 38.874) -> (-36.9171, 39.0413)
  line L22 (-36.4992, 38.7061) -> (-36.7081, 38.874)
  line L23 (-36.2905, 38.5376) -> (-36.4992, 38.7061)
  line L24 (-36.082, 38.3687) -> (-36.2905, 38.5376)
  line L25 (-35.8737, 38.1992) -> (-36.082, 38.3687)
  line L26 (-35.6656, 38.0292) -> (-35.8737, 38.1992)
  line L27 (-35.4577, 37.8588) -> (-35.6656, 38.0292)
  line L28 (-35.25, 37.688) -> (-35.4577, 37.8588)
  line L29 (-35.0425, 37.5167) -> (-35.25, 37.688)
  line L30 (-34.8352, 37.3451) -> (-35.0425, 37.5167)
  line L31 (-34.6282, 37.173) -> (-34.8352, 37.3451)
  line L32 (-34.4215, 37.0006) -> (-34.6282, 37.173)
  line L33 (-34.215, 36.8278) -> (-34.4215, 37.0006)
  line L34 (-34.0088, 36.6547) -> (-34.215, 36.8278)
  line L35 (-33.8028, 36.4812) -> (-34.0088, 36.6547)
  line L36 (-33.5972, 36.3074) -> (-33.8028, 36.4812)
  line L37 (-33.392, 36.1333) -> (-33.5972, 36.3074)
  line L38 (-33.187, 35.9589) -> (-33.392, 36.1333)
  line L39 (-32.9825, 35.7842) -> (-33.187, 35.9589)
  line L40 (-32.7783, 35.6093) -> (-32.9825, 35.7842)
  line L41 (-32.5745, 35.434) -> (-32.7783, 35.6093)
  line L42 (-32.3711, 35.2584) -> (-32.5745, 35.434)
  line L43 (-32.1682, 35.0826) -> (-32.3711, 35.2584)
  line L44 (-31.9657, 34.9065) -> (-32.1682, 35.0826)
  line L45 (-31.7637, 34.7302) -> (-31.9657, 34.9065)
  line L46 (-31.5623, 34.5535) -> (-31.7637, 34.7302)
  line L47 (-31.3613, 34.3766) -> (-31.5623, 34.5535)
  line L48 (-31.1609, 34.1994) -> (-31.3613, 34.3766)
  line L49 (-30.9611, 34.0219) -> (-31.1609, 34.1994)
  line L50 (-30.7619, 33.8442) -> (-30.9611, 34.0219)
  line L51 (-30.5634, 33.6662) -> (-30.7619, 33.8442)
  line L52 (-30.3654, 33.4878) -> (-30.5634, 33.6662)
  line L53 (-30.1682, 33.3092) -> (-30.3654, 33.4878)
  line L54 (-29.9717, 33.1303) -> (-30.1682, 33.3092)
  line L55 (-29.7759, 32.9511) -> (-29.9717, 33.1303)
  line L56 (-29.5809, 32.7715) -> (-29.7759, 32.9511)
  line L57 (-29.3866, 32.5916) -> (-29.5809, 32.7715)
  line L58 (-29.1932, 32.4114) -> (-29.3866, 32.5916)
  line L59 (-29.0007, 32.2308) -> (-29.1932, 32.4114)
  line L60 (-28.809, 32.0499) -> (-29.0007, 32.2308)
  line L61 (-28.6182, 31.8686) -> (-28.809, 32.0499)
  line L62 (-28.4284, 31.6869) -> (-28.6182, 31.8686)
  line L63 (-28.2395, 31.5048) -> (-28.4284, 31.6869)
  line L64 (-28.0516, 31.3224) -> (-28.2395, 31.5048)
  line L65 (-27.8647, 31.1395) -> (-28.0516, 31.3224)
  line L66 (-27.6789, 30.9562) -> (-27.8647, 31.1395)
  line L67 (-27.4942, 30.7724) -> (-27.6789, 30.9562)
  line L68 (-27.3106, 30.5882) -> (-27.4942, 30.7724)
  line L69 (-27.1281, 30.4035) -> (-27.3106, 30.5882)
  line L70 (-26.9468, 30.2184) -> (-27.1281, 30.4035)
  line L71 (-26.7667, 30.0327) -> (-26.9468, 30.2184)
  line L72 (-26.5878, 29.8465) -> (-26.7667, 30.0327)
  line L73 (-26.4102, 29.6599) -> (-26.5878, 29.8465)
  line L74 (-26.2338, 29.4727) -> (-26.4102, 29.6599)
  line L75 (-26.0588, 29.2849) -> (-26.2338, 29.4727)
  line L76 (-25.8851, 29.0966) -> (-26.0588, 29.2849)
  line L77 (-25.7127, 28.9078) -> (-25.8851, 29.0966)
  line L78 (-25.5418, 28.7183) -> (-25.7127, 28.9078)
  line L79 (-25.3723, 28.5283) -> (-25.5418, 28.7183)
  line L80 (-25.2042, 28.3376) -> (-25.3723, 28.5283)
  line L81 (-25.0376, 28.1464) -> (-25.2042, 28.3376)
  line L82 (-24.8725, 27.9545) -> (-25.0376, 28.1464)
  line L83 (-24.7089, 27.762) -> (-24.8725, 27.9545)
  line L84 (-24.5469, 27.5688) -> (-24.7089, 27.762)
  line L85 (-24.3864, 27.375) -> (-24.5469, 27.5688)
  line L86 (-24.2275, 27.1805) -> (-24.3864, 27.375)
  line L87 (-24.0703, 26.9854) -> (-24.2275, 27.1805)
  line L88 (-23.9146, 26.7895) -> (-24.0703, 26.9854)
  line L89 (-23.7607, 26.593) -> (-23.9146, 26.7895)
  line L90 (-23.6084, 26.3958) -> (-23.7607, 26.593)
  line L91 (-23.4578, 26.1978) -> (-23.6084, 26.3958)
  line L92 (-23.3089, 25.9992) -> (-23.4578, 26.1978)
  line L93 (-23.1618, 25.7998) -> (-23.3089, 25.9992)
  line L94 (-23.0164, 25.5997) -> (-23.1618, 25.7998)
  line L95 (-22.8728, 25.3988) -> (-23.0164, 25.5997)
  line L96 (-22.7309, 25.1972) -> (-22.8728, 25.3988)
  line L97 (-22.5909, 24.9949) -> (-22.7309, 25.1972)
  line L98 (-22.4527, 24.7917) -> (-22.5909, 24.9949)
  line L99 (-22.3163, 24.5879) -> (-22.4527, 24.7917)
  line L100 (-22.1817, 24.3832) -> (-22.3163, 24.5879)
  line L101 (-22.049, 24.1778) -> (-22.1817, 24.3832)
  line L102 (-21.9182, 23.9716) -> (-22.049, 24.1778)
  line L103 (-21.7892, 23.7646) -> (-21.9182, 23.9716)
  line L104 (-21.6622, 23.5568) -> (-21.7892, 23.7646)
  line L105 (-21.537, 23.3482) -> (-21.6622, 23.5568)
  line L106 (-21.4137, 23.1388) -> (-21.537, 23.3482)
  line L107 (-21.2923, 22.9286) -> (-21.4137, 23.1388)
  line L108 (-21.1728, 22.7176) -> (-21.2923, 22.9286)
  line L109 (-21.0553, 22.5058) -> (-21.1728, 22.7176)
  line L110 (-20.9397, 22.2931) -> (-21.0553, 22.5058)
  line L111 (-20.8259, 22.0796) -> (-20.9397, 22.2931)
  line L112 (-20.7142, 21.8653) -> (-20.8259, 22.0796)
  line L113 (-20.6043, 21.6502) -> (-20.7142, 21.8653)
  line L114 (-20.4964, 21.4342) -> (-20.6043, 21.6502)
  line L115 (-20.3904, 21.2174) -> (-20.4964, 21.4342)
  line L116 (-20.2863, 20.9997) -> (-20.3904, 21.2174)
  line L117 (-20.1842, 20.7812) -> (-20.2863, 20.9997)
  line L118 (-20.0839, 20.5618) -> (-20.1842, 20.7812)
  line L119 (-19.9856, 20.3416) -> (-20.0839, 20.5618)
  line L120 (-19.8892, 20.1205) -> (-19.9856, 20.3416)
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extrude "Extrude1" new body sketch "Roller compensated replaceable cam" along normal blind 8 bodies "P08 Cam 3 gates - stable endpoints"
work_plane "WorkPlane2" AlongDistance 6.9 ExtraOffset 0
sketch "Cam screw clearance" plane through (6.9, 0, 0) normal (1, 0, 0) x axis (0, 0, -1)
  circle C1 centre (-39.5442, 25.4558) radius 1.7
extrude "Extrude2" cut sketch "Cam screw clearance" along normal blind 8.2
work_plane "WorkPlane3" AlongDistance 12 ExtraOffset 0
sketch "Cam head recess" plane through (12, 0, 0) normal (1, 0, 0) x axis (0, 0, -1)
  circle C1 centre (-39.5442, 25.4558) radius 3.1
extrude "Extrude3" cut sketch "Cam head recess" along normal blind 3.1
work_plane "WorkPlane4" AlongDistance 6.9 ExtraOffset 0
sketch "Cam screw clearance (1)" plane through (6.9, 0, 0) normal (1, 0, 0) x axis (0, 0, -1)
  circle C1 centre (-29, 0) radius 1.7
extrude "Extrude4" cut sketch "Cam screw clearance (1)" along normal blind 8.2
work_plane "WorkPlane5" AlongDistance 12 ExtraOffset 0
sketch "Cam head recess (1)" plane through (12, 0, 0) normal (1, 0, 0) x axis (0, 0, -1)
  circle C1 centre (-29, 0) radius 3.1
extrude "Extrude5" cut sketch "Cam head recess (1)" along normal blind 3.1
work_plane "WorkPlane6" AlongDistance 6.9 ExtraOffset 0
sketch "Cam screw clearance (2)" plane through (6.9, 0, 0) normal (1, 0, 0) x axis (0, 0, -1)
  circle C1 centre (-39.5442, -25.4558) radius 1.7
extrude "Extrude6" cut sketch "Cam screw clearance (2)" along normal blind 8.2
work_plane "WorkPlane7" AlongDistance 12 ExtraOffset 0
sketch "Cam head recess (2)" plane through (12, 0, 0) normal (1, 0, 0) x axis (0, 0, -1)
  circle C1 centre (-39.5442, -25.4558) radius 3.1
extrude "Extrude7" cut sketch "Cam head recess (2)" along normal blind 3.1
work_plane "WorkPlane1" AlongDistance 0 ExtraOffset 0
sketch "Palm grip smooth contour" plane through (0, 0, 0) normal (1, 0, 0) x axis (0, 0, -1)
  curve K1 (-225, 0) -> (-165, 12)
  line L1 (-225, 0) -> (-165, 0)
  line L2 (-165, 12) -> (-165, 0)
revolve "Revolve1" sketch "Palm grip smooth contour" AlongAngle 360 bodies "P09 Grip insert half"
work_plane "WorkPlane2" AlongDistance 0 ExtraOffset 0
sketch "Split on print bed face" plane through (0, 0, 0) normal (1, 0, 0) x axis (0, 0, -1)
  line L1 (-160, 30) -> (-160, -30)
  line L2 (-230, 30) -> (-160, 30)
  line L3 (-230, -30) -> (-230, 30)
  line L4 (-160, -30) -> (-230, -30)
extrude "Extrude1" cut sketch "Split on print bed face" along normal blind 30
work_plane "WorkPlane3" AlongDistance -7.2 ExtraOffset 0
sketch "Keyed stem socket" plane through (-7.2, 0, 0) normal (1, 0, 0) x axis (0, 0, -1)
  line L1 (-164, 7.2) -> (-164, -7.2)
  line L2 (-196, 7.2) -> (-164, 7.2)
  line L3 (-196, -7.2) -> (-196, 7.2)
  line L4 (-164, -7.2) -> (-196, -7.2)
extrude "Extrude2" cut sketch "Keyed stem socket" along normal blind 14.4
work_plane "WorkPlane4" AlongDistance -13.9 ExtraOffset 0
sketch "M3 grip heat set" plane through (-13.9, 0, 0) normal (1, 0, 0) x axis (0, 0, -1)
  circle C1 centre (-180, 0) radius 2
extrude "Extrude3" cut sketch "M3 grip heat set" along normal blind 6.8
work_plane "WorkPlane5" AlongDistance -13.9 ExtraOffset 0
sketch "M3 grip heat set (1)" plane through (-13.9, 0, 0) normal (1, 0, 0) x axis (0, 0, -1)
  circle C1 centre (-190, 0) radius 2
extrude "Extrude4" cut sketch "M3 grip heat set (1)" along normal blind 6.8
work_plane "WorkPlane1" AlongDistance 0 ExtraOffset 0
sketch "Palm grip smooth contour" plane through (0, 0, 0) normal (1, 0, 0) x axis (0, 0, -1)
  curve K1 (-225, 0) -> (-165, 12)
  line L1 (-225, 0) -> (-165, 0)
  line L2 (-165, 12) -> (-165, 0)
revolve "Revolve1" sketch "Palm grip smooth contour" AlongAngle 360 bodies "P10 Grip screw half"
work_plane "WorkPlane2" AlongDistance -30 ExtraOffset 0
sketch "Split on print bed face" plane through (-30, 0, 0) normal (1, 0, 0) x axis (0, 0, -1)
  line L1 (-160, 30) -> (-160, -30)
  line L2 (-230, 30) -> (-160, 30)
  line L3 (-230, -30) -> (-230, 30)
  line L4 (-160, -30) -> (-230, -30)
extrude "Extrude1" cut sketch "Split on print bed face" along normal blind 30
work_plane "WorkPlane3" AlongDistance -7.2 ExtraOffset 0
sketch "Keyed stem socket" plane through (-7.2, 0, 0) normal (1, 0, 0) x axis (0, 0, -1)
  line L1 (-164, 7.2) -> (-164, -7.2)
  line L2 (-196, 7.2) -> (-164, 7.2)
  line L3 (-196, -7.2) -> (-196, 7.2)
  line L4 (-164, -7.2) -> (-196, -7.2)
extrude "Extrude2" cut sketch "Keyed stem socket" along normal blind 14.4
work_plane "WorkPlane4" AlongDistance -0.1 ExtraOffset 0
sketch "Grip screw bore" plane through (-0.1, 0, 0) normal (1, 0, 0) x axis (0, 0, -1)
  circle C1 centre (-180, 0) radius 1.7
extrude "Extrude3" cut sketch "Grip screw bore" along normal blind 26
work_plane "WorkPlane5" AlongDistance 12.5 ExtraOffset 0
sketch "Recessed grip screw head" plane through (12.5, 0, 0) normal (1, 0, 0) x axis (0, 0, -1)
  circle C1 centre (-180, 0) radius 3.1
extrude "Extrude4" cut sketch "Recessed grip screw head" along normal blind 14
work_plane "WorkPlane6" AlongDistance -0.1 ExtraOffset 0
sketch "Grip screw bore (1)" plane through (-0.1, 0, 0) normal (1, 0, 0) x axis (0, 0, -1)
  circle C1 centre (-190, 0) radius 1.7
extrude "Extrude5" cut sketch "Grip screw bore (1)" along normal blind 26
work_plane "WorkPlane7" AlongDistance 12.5 ExtraOffset 0
sketch "Recessed grip screw head (1)" plane through (12.5, 0, 0) normal (1, 0, 0) x axis (0, 0, -1)
  circle C1 centre (-190, 0) radius 3.1
extrude "Extrude6" cut sketch "Recessed grip screw head (1)" along normal blind 14
work_plane "WorkPlane1" AlongDistance 4 ExtraOffset 0
sketch "First strong flat cheek" plane through (4, 0, 0) normal (1, 0, 0) x axis (0, 0, -1)
  line L1 (-6, -5) -> (-6, -61)
  line L2 (-7, 0) -> (-6, -5)
  line L3 (-17, 0) -> (-7, 0)
  line L4 (-18, -5) -> (-17, 0)
  line L5 (-18, -61) -> (-18, -5)
  line L6 (-6, -61) -> (-18, -61)
extrude "Extrude1" new body sketch "First strong flat cheek" along normal blind 3 bodies "P11 Forked roller follower"
work_plane "WorkPlane2" AlongDistance 4 ExtraOffset 0
sketch "Spring tail bridge" plane through (4, 0, 0) normal (1, 0, 0) x axis (0, 0, -1)
  line L1 (-6, -49) -> (-6, -61)
  line L2 (-18, -49) -> (-6, -49)
  line L3 (-18, -61) -> (-18, -49)
  line L4 (-6, -61) -> (-18, -61)
extrude "Extrude2" add sketch "Spring tail bridge" along normal blind 16
work_plane "WorkPlane3" AlongDistance 17 ExtraOffset 0
sketch "Second supporting cheek" plane through (17, 0, 0) normal (1, 0, 0) x axis (0, 0, -1)
  line L1 (-6, -5) -> (-6, -61)
  line L2 (-7, 0) -> (-6, -5)
  line L3 (-17, 0) -> (-7, 0)
  line L4 (-18, -5) -> (-17, 0)
  line L5 (-18, -61) -> (-18, -5)
  line L6 (-6, -61) -> (-18, -61)
extrude "Extrude3" add sketch "Second supporting cheek" along normal blind 3
work_plane "WorkPlane4" AlongDistance 4 ExtraOffset 0
sketch "Rounded roller cheek" plane through (4, 0, 0) normal (1, 0, 0) x axis (0, 0, -1)
  circle C1 centre (-12, 0) radius 6
extrude "Extrude4" add sketch "Rounded roller cheek" along normal blind 3
work_plane "WorkPlane5" AlongDistance 17 ExtraOffset 0
sketch "Rounded roller cheek (1)" plane through (17, 0, 0) normal (1, 0, 0) x axis (0, 0, -1)
  circle C1 centre (-12, 0) radius 6
extrude "Extrude5" add sketch "Rounded roller cheek (1)" along normal blind 3
work_plane "WorkPlane6" AlongDistance 3.9 ExtraOffset 0
sketch "Smooth pivot sleeve bore" plane through (3.9, 0, 0) normal (1, 0, 0) x axis (0, 0, -1)
  circle C1 centre (-12, -35) radius 4.15
extrude "Extrude6" cut sketch "Smooth pivot sleeve bore" along normal blind 16.2
work_plane "WorkPlane7" AlongDistance 3.9 ExtraOffset 0
sketch "Roller axle holes" plane through (3.9, 0, 0) normal (1, 0, 0) x axis (0, 0, -1)
  circle C1 centre (-12, 0) radius 1.7
extrude "Extrude7" cut sketch "Roller axle holes" along normal blind 16.2
work_plane "WorkPlane8" AlongDistance 3.9 ExtraOffset 0
sketch "Roller M3 nut recess" plane through (3.9, 0, 0) normal (1, 0, 0) x axis (0, 0, -1)
  line L1 (-14.9, 1.6743) -> (-12, 3.3486)
  line L2 (-14.9, -1.6743) -> (-14.9, 1.6743)
  line L3 (-12, -3.3486) -> (-14.9, -1.6743)
  line L4 (-9.1, -1.6743) -> (-12, -3.3486)
  line L5 (-9.1, 1.6743) -> (-9.1, -1.6743)
  line L6 (-12, 3.3486) -> (-9.1, 1.6743)
extrude "Extrude8" cut sketch "Roller M3 nut recess" along normal blind 1.6
work_plane "WorkPlane9" AlongDistance 18 ExtraOffset 0
sketch "Spring tail locating pilot" plane through (0, 0, 18) normal (0, 0, 1) x axis (1, 0, 0)
  circle C1 centre (12, -55) radius 1.8
extrude "Extrude9" add sketch "Spring tail locating pilot" along normal blind 2
work_plane "WorkPlane1" AlongDistance 7.25 ExtraOffset 0
sketch "10 mm roller" plane through (7.25, 0, 0) normal (1, 0, 0) x axis (0, 0, -1)
  circle C1 centre (-12, 0) radius 5
extrude "Extrude1" new body sketch "10 mm roller" along normal blind 9.5 bodies "P12 Replaceable plain roller"
work_plane "WorkPlane2" AlongDistance 7.1 ExtraOffset 0
sketch "Roller spacer tube bore" plane through (7.1, 0, 0) normal (1, 0, 0) x axis (0, 0, -1)
  circle C1 centre (-12, 0) radius 2.15
extrude "Extrude2" cut sketch "Roller spacer tube bore" along normal blind 9.8
work_plane "WorkPlane1" AlongDistance -24 ExtraOffset 0
sketch "Captured spring reaction block" plane through (-24, 0, 0) normal (1, 0, 0) x axis (0, 0, -1)
  line L1 (-38, -44) -> (-38, -66)
  line L2 (-52, -44) -> (-38, -44)
  line L3 (-52, -66) -> (-52, -44)
  line L4 (-38, -66) -> (-52, -66)
extrude "Extrude1" new body sketch "Captured spring reaction block" along normal blind 48
work_plane "WorkPlane2" AlongDistance -24.1 ExtraOffset 0
sketch "Left M3 insert with screw tip relief" plane through (-24.1, 0, 0) normal (1, 0, 0) x axis (0, 0, -1)
  circle C1 centre (-44, -59) radius 2
extrude "Extrude2" cut sketch "Left M3 insert with screw tip relief" along normal blind 8.8
work_plane "WorkPlane3" AlongDistance 15.3 ExtraOffset 0
sketch "Right M3 insert with screw tip relief" plane through (15.3, 0, 0) normal (1, 0, 0) x axis (0, 0, -1)
  circle C1 centre (-44, -59) radius 2
extrude "Extrude3" cut sketch "Right M3 insert with screw tip relief" along normal blind 8.8
work_plane "WorkPlane4" AlongDistance -24.1 ExtraOffset 0
sketch "Left M3 insert with screw tip relief (1)" plane through (-24.1, 0, 0) normal (1, 0, 0) x axis (0, 0, -1)
  circle C1 centre (-44, -51) radius 2
extrude "Extrude4" cut sketch "Left M3 insert with screw tip relief (1)" along normal blind 8.8
work_plane "WorkPlane5" AlongDistance 15.3 ExtraOffset 0
sketch "Right M3 insert with screw tip relief (1)" plane through (15.3, 0, 0) normal (1, 0, 0) x axis (0, 0, -1)
  circle C1 centre (-44, -51) radius 2
extrude "Extrude5" cut sketch "Right M3 insert with screw tip relief (1)" along normal blind 8.8
work_plane "WorkPlane6" AlongDistance 37.9 ExtraOffset 0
